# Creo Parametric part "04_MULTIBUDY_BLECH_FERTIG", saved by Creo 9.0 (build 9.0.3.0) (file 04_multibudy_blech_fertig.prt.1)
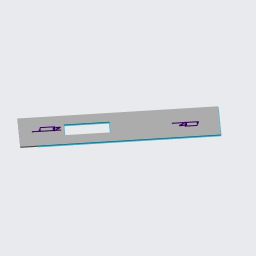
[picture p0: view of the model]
Materials in the file: S235JRG2

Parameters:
  BENENNUNG = "XXX"
  DATUM = "XX.XX.XX"
  ERSTELLER = "ARINDA"
  TEILETYP = "Fertigungsteil"
  SMT_DFLT_BEND_REL_LENGTH_TYPE = "Through All"
  PTC_MASTER_MATERIAL = "S235JRG2"
  SELECT_EN_NAME = "S235JRG2"
  SELECT_DIN_NAME = "RSt37-2"
  SELECT_DIN_NUMBER = "1.0038"
  SELECT_ASTM_NAME = "A 283 M Grade 2"
  MATERIAL_GROUP = "ME_ST_Baustahl"
  STANDARD_EN_DELIVERYSPEC = "DIN EN 10025"
  STANDARD_DIN_DELIVERYSPEC = "DIN 17100"

Other parameters: MASSE, SMT_THICKNESS, SMT_PART_BEND_ALLOWANCE_FACTOR, SMT_DFLT_BEND_RADIUS, SMT_DFLT_BEND_ANGLE, SMT_DFLT_CRNR_REL_WIDTH, SMT_DFLT_CRNR_REL_DEPTH, SMT_DFLT_BEND_REL_WIDTH, SMT_DFLT_BEND_REL_DEPTH, SMT_DFLT_BEND_REL_LENGTH, SMT_DFLT_BEND_REL_ANGLE, SMT_GAP, SMT_DFLT_EDGE_TREA_WIDTH, SMT_DFLT_MITER_CUT_WIDTH, SMT_DFLT_MITER_CUT_OFFSET, SMT_FLAT_PATTERN_LENGTH, D14, D15, D16, D17, D18, D19, D20, D21, D25, D29, D50, D51, D52, D53, D54, D55, D56, D57, D58

Created from: ARINDA-STARTTEIL.PRT

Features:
  1. coordinate system
  2. datum plane "T_RECHTS_Y-Z"
  3. datum plane "T_OBEN_X-Z"
  4. datum plane "T_VORNE_X-Y"
  5. datum axis
  6. datum axis
  7. datum axis
  8. sketch "Skizze 1"
  9. extrusion "Profil 1"
  10. feature "Konvertieren(Erste Lasche)"
  11. feature "Biegen 1"
  12. feature "Flange 1"
  13. feature "Endabwicklung 1"
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
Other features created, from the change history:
  feature "Abwickeln 1"

Other named items: T_BASIC, T_X-ACHSE, T_Y-ACHSE, T_Z-ACHSE, FLAT_PATTERN_WIDTH, FLAT_PATTERN_LENGTH

Layers: 00_STD-ACHSEN, 00_STD-EBENEN, 00_STD-KOORDSYS, 01_ACHSEN, 01_KURVEN, KURVENELEMENTE, VOLUMENGEOMETRIE

Notes: 20.00° | 180.00°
